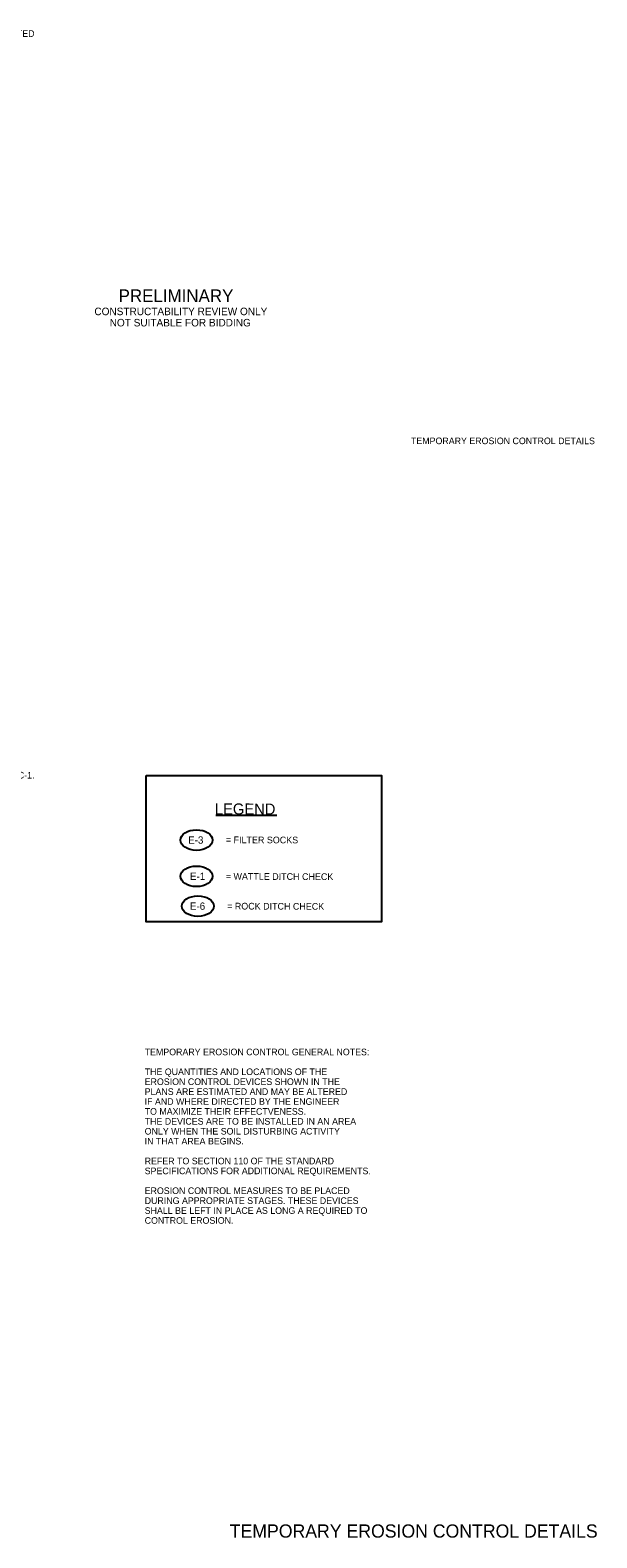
# Model space of a CAD drawing. Extents: x 1929624 to 1932072, y 596315 to 605954.
# Drawn here: x 1931557 to 1932072, y 604548 to 605917 of the extents above; entities that cross this region are included whole.
import ezdxf

# ---------------------------------------------------------------- set-up
doc = ezdxf.new("R2010")
doc.units = 0
for name, color, linetype in [('B_Concrete', 7, 'Continuous'), ('B_Concrete hidden', 7, 'Continuous'), ('B_Copy In', 7, 'Continuous'), ('Default', 7, 'Continuous')]:
    doc.layers.add(name, color=color, linetype=linetype)

msp = doc.modelspace()

# ---------------------------------------------------------------- linework, layer by layer
at = {"layer": 'B_Concrete hidden'}
msp.add_line((1931725.6, 605204.2), (1931781.1, 605204.2), dxfattribs=at)
msp.add_lwpolyline([(1931662.3, 605240.1), (1931876, 605240.1), (1931876, 605107.3), (1931662.3, 605107.3)], close=True, dxfattribs=at)
for centre in [(1931708, 605181.6), (1931708, 605148.7), (1931709.2, 605121.6)]:
    msp.add_ellipse(centre, major_axis=(14.6, 0), ratio=0.638788, dxfattribs=at)

# ---------------------------------------------------------------- texts
at = {"layer": 'B_Concrete'}
msp.add_text('TEMPORARY EROSION CONTROL DETAILS ', height=6, rotation=359.9934, dxfattribs=at).set_placement((1931902.9, 605541.1))
at = {"layer": 'B_Concrete hidden'}
for s, p in [('E-3', (1931700.4, 605178.3)), ('E-1', (1931702.1, 605145.4)), ('E-6', (1931702, 605118.3))]:
    msp.add_text(s, height=6.66, rotation=360, dxfattribs=at).set_placement(p)
for s, height, p in [('TEMPORARY EROSION CONTROL GENERAL NOTES:', 6, (1931660.9, 604986.2)), ('THE QUANTITIES AND LOCATIONS OF THE', 6, (1931660.9, 604968.2)), ('EROSION CONTROL DEVICES SHOWN IN THE ', 6, (1931660.9, 604959.2)), ('PLANS ARE ESTIMATED AND MAY BE ALTERED ', 6, (1931660.9, 604950.2)), ('TO MAXIMIZE THEIR EFFECTVENESS. ', 6, (1931660.9, 604932.2)), ('IF AND WHERE DIRECTED BY THE ENGINEER ', 6, (1931660.9, 604941.2)), ('THE DEVICES ARE TO BE INSTALLED IN AN AREA ', 6, (1931660.9, 604923.2)), ('ONLY WHEN THE SOIL DISTURBING ACTIVITY', 6, (1931660.9, 604914.2)), ('IN THAT AREA BEGINS.', 6, (1931660.9, 604905.2)), ('SPECIFICATIONS FOR ADDITIONAL REQUIREMENTS.', 6, (1931660.9, 604878.2)), ('REFER TO SECTION 110 OF THE STANDARD ', 6, (1931660.9, 604887.2)), ('EROSION CONTROL MEASURES TO BE PLACED', 6, (1931660.9, 604860.2)), ('DURING APPROPRIATE STAGES. THESE DEVICES', 6, (1931660.9, 604851.2)), ('SHALL BE LEFT IN PLACE AS LONG A REQUIRED TO ', 6, (1931660.9, 604842.2)), ('CONTROL EROSION.', 6, (1931660.9, 604833.2)), ('TEMPORARY EROSION CONTROL DETAILS', 12, (1931738.2, 604548.2))]:
    msp.add_text(s, height=height, dxfattribs=at).set_placement(p)
at = {"layer": 'B_Copy In'}
for s, height, p in [('PRELIMINARY', 11.508, (1931637.2, 605670.1)), ('CONSTRUCTABILITY REVIEW ONLY', 6.823, (1931615.2, 605658.2)), ('NOT SUITABLE FOR BIDDING', 6.823, (1931629.1, 605648))]:
    msp.add_text(s, height=height, rotation=0, dxfattribs=at).set_placement(p)
at = {"layer": 'Default'}
for s, p in [('IF AND WHERE DIRECTED', (1931459.2, 605910.9)), ('SECTION. REFER TO STD. DWG. TEC-1.', (1931407.9, 605237.5))]:
    msp.add_text(s, height=6, dxfattribs=at).set_placement(p)
for s, height, p in [('LEGEND', 10, (1931724.7, 605204.9)), ('= FILTER SOCKS', 6.075, (1931734.7, 605178.8)), ('= WATTLE DITCH CHECK', 6.075, (1931734.6, 605145.6)), ('= ROCK DITCH CHECK', 6.075, (1931735.8, 605118.6))]:
    msp.add_text(s, height=height, rotation=359.8271, dxfattribs=at).set_placement(p)

doc.saveas('drawing.dxf')
